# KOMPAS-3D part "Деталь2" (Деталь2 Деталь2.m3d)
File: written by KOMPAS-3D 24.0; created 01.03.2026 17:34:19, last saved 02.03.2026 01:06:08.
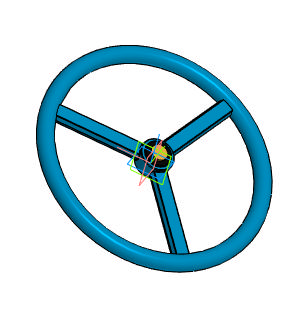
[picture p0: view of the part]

Document properties: Автор: R2D2; Полное имя файла: E:\Работа\Зайцев\GVWR3131M-2W-F-S Задвижка клиновая с выдвижным штоком DN.ru Ду50-200 Ру63\DN100\исходные материалы\Деталь2 Деталь2.m3d

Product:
- Body: Твердое тело1  | qty 1
    Масса: 4.922929
- Part/product: Деталь2
    Масса: 4.922929
    additional columns: Типовые

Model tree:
1. Твердое тело1  (labels: Твердое тело1)
2. Эскиз:1
3. Элемент выдавливания:1
     Расстояние 1 = 100
4. Эскиз:2
5. Элемент вращения:1
     Угол 1 = 360
6. Элемент выдавливания:2  (with: Грань.Элемент выдавливания:1, Грань.Элемент вращения:1)
     Расстояние 2 = 92.9664
7. Массив по концентрической сетке:1  (with: Элемент выдавливания:2)  (labels: Грань.Твердое тело1)  (3 pattern instances)
     Шаг 2 = 360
